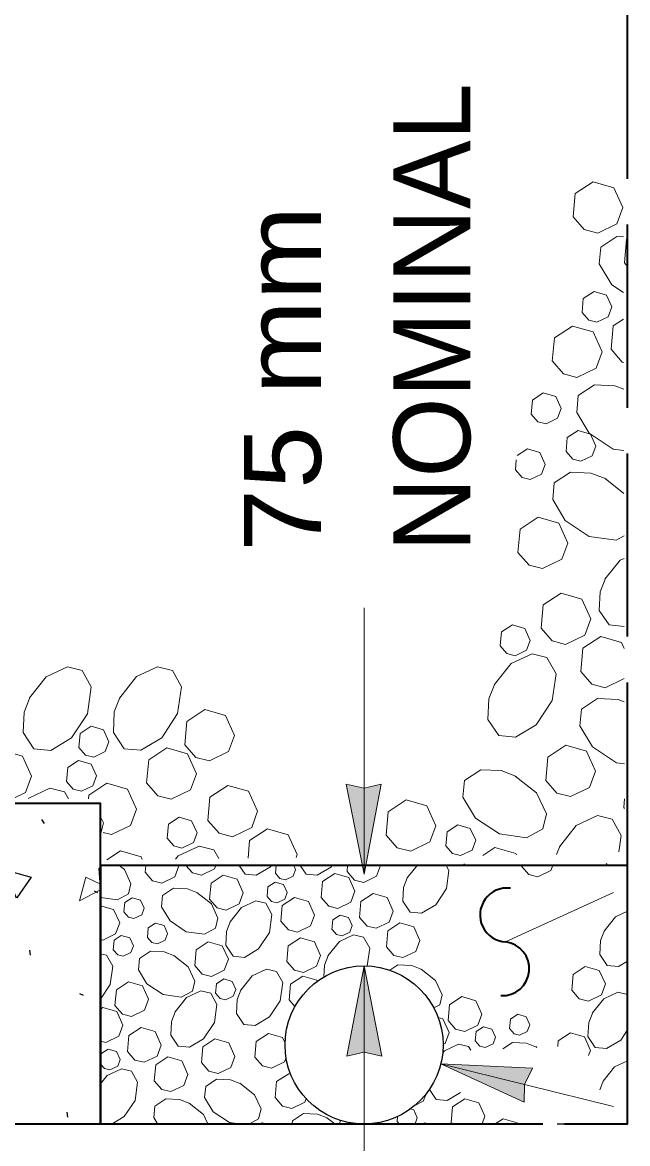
# Model space of a CAD drawing. Extents: x 17672 to 18472, y -9785 to -9267.
# Drawn here: x 17840.7 to 17868.5, y -9467.9 to -9416.4 of the extents above; entities that cross this region are included whole.
import ezdxf

# ---------------------------------------------------------------- set-up
doc = ezdxf.new("R2010")
doc.units = 0
doc.header["$LTSCALE"] = 1.4
doc.linetypes.add('LONG_DASHED', pattern=[7.5, 6, -1.5])
for name, color, linetype, lineweight in [('1', 7, 'Continuous', 13), ('15', 7, 'Continuous', 13), ('16', 7, 'Continuous', 13)]:
    doc.layers.add(name, color=color, linetype=linetype, lineweight=lineweight)
doc.layers.add('19', color=7, linetype='Continuous')

msp = doc.modelspace()

# ---------------------------------------------------------------- hatches: boundary and pattern name
at = {"layer": '16'}
for points in [[(17856.379, -9455.509), (17857.161, -9451.372), (17856.379, -9451.558), (17855.558, -9451.372)], [(17856.379, -9459.715), (17855.597, -9463.852), (17856.379, -9463.666), (17857.2, -9463.852)], [(17859.898, -9464.208), (17863.729, -9465.958), (17863.737, -9465.151), (17864.112, -9464.401)]]:
    msp.add_hatch(color=256, dxfattribs=at).paths.add_polyline_path(points)

# ---------------------------------------------------------------- linework, layer by layer
at = {"layer": '1', "linetype": 'LONG_DASHED', "lineweight": 35}
msp.add_line((17868.469, -9455.105), (17868.469, -9325.672), dxfattribs=at)
at = {"layer": '1'}
for p, q in [((17868.469, -9427.626), (17868.322, -9427.457)), ((17863.32, -9436.959), (17863.361, -9436.503)), ((17867.434, -9437.35), (17868.301, -9438.036)), ((17868.291, -9452.451), (17868.328, -9452.042)), ((17868.328, -9452.493), (17868.292, -9452.451)), ((17865.213, -9454.602), (17865.372, -9454.195)), ((17846.334, -9455.416), (17846.361, -9455.105)), ((17852.315, -9455.465), (17852.347, -9455.105)), ((17855.599, -9455.382), (17855.624, -9455.105)), ((17858.362, -9455.676), (17858.815, -9455.105)), ((17861.027, -9455.105), (17860.963, -9455.031)), ((17863.589, -9455.124), (17863.592, -9455.105)), ((17867.564, -9455.105), (17867.486, -9455.016)), ((17844.288, -9456.22), (17843.322, -9456.73)), ((17853.21, -9461.58), (17852.942, -9461.271)), ((17864.264, -9463.418), (17864.305, -9463.453)), ((17867.19, -9465.406), (17867.362, -9464.972)), ((17857.896, -9466.855), (17857.915, -9466.622)), ((17854.678, -9466.678), (17855.04, -9466.965)), ((17855.261, -9466.965), (17855.278, -9466.793)), ((17856.707, -9466.95), (17856.702, -9466.965)), ((17857.994, -9466.965), (17857.896, -9466.855)), ((17860.435, -9466.965), (17860.379, -9466.901))]:
    msp.add_line(p, q, dxfattribs=at)
at = {"layer": '1', "lineweight": 25}
for p, q in [((17841.579, -9452.997), (17841.71, -9453.175)), ((17843.991, -9456.27), (17844.149, -9456.349)), ((17844.288, -9455.897), (17844.278, -9455.908)), ((17841.073, -9459.228), (17841.048, -9458.988)), ((17843.327, -9460.977), (17843.486, -9461.055)), ((17842.791, -9466.659), (17842.766, -9466.418)), ((17865.232, -9466.965), (17865.57, -9466.965))]:
    msp.add_line(p, q, dxfattribs=at)
at = {"layer": '1'}
for points in [[(17865.97, -9425.35), (17866.065, -9424.279), (17866.891, -9423.737), (17867.841, -9424.01), (17868.253, -9424.923), (17867.979, -9425.666), (17867.1, -9426.092), (17866.481, -9425.936), (17865.97, -9425.349)], [(17868.284, -9428.821), (17867.742, -9428.463), (17867.167, -9427.507), (17867.24, -9426.74), (17867.98, -9426.244), (17868.279, -9426.258)], [(17868.321, -9427.457), (17868.417, -9426.387), (17868.469, -9426.352)], [(17866.38, -9429.739), (17866.438, -9429.097), (17866.933, -9428.771), (17867.503, -9428.935), (17867.75, -9429.482), (17867.586, -9429.929), (17867.058, -9430.184), (17866.687, -9430.091), (17866.381, -9429.738)], [(17867.715, -9431.421), (17867.811, -9430.351), (17868.286, -9430.039)], [(17865.017, -9431.97), (17865.113, -9430.9), (17865.939, -9430.358), (17866.888, -9430.631), (17867.301, -9431.544), (17867.027, -9432.288), (17866.147, -9432.713), (17865.528, -9432.558), (17865.018, -9431.97)], [(17868.29, -9432.024), (17868.226, -9432.008), (17867.715, -9431.421)], [(17868.297, -9436.072), (17867.815, -9436.003), (17866.711, -9435.274), (17866.136, -9434.318), (17866.209, -9433.551), (17866.948, -9433.055), (17867.891, -9433.099), (17868.292, -9433.256)], [(17864.049, -9434.397), (17864.106, -9433.755), (17864.602, -9433.429), (17865.172, -9433.593), (17865.419, -9434.141), (17865.255, -9434.587), (17864.727, -9434.842), (17864.356, -9434.749), (17864.05, -9434.397)], [(17865.645, -9436.118), (17865.703, -9435.476), (17866.198, -9435.151), (17866.768, -9435.315), (17867.015, -9435.862), (17866.851, -9436.308), (17866.324, -9436.564), (17865.952, -9436.471), (17865.646, -9436.118)], [(17863.406, -9436.298), (17863.873, -9435.991), (17864.443, -9436.155), (17864.69, -9436.703), (17864.526, -9437.149), (17863.998, -9437.405), (17863.627, -9437.311), (17863.321, -9436.959)], [(17868.305, -9439.981), (17867.943, -9440.181), (17866.712, -9440.007), (17865.608, -9439.277), (17865.033, -9438.322), (17865.106, -9437.554), (17865.846, -9437.059), (17866.788, -9437.102), (17867.483, -9437.375)], [(17863.441, -9440.743), (17863.536, -9439.672), (17864.363, -9439.13), (17865.312, -9439.403), (17865.725, -9440.316), (17865.45, -9441.06), (17864.571, -9441.485), (17863.952, -9441.329), (17863.441, -9440.742)], [(17867.432, -9441.977), (17868.127, -9441.1), (17868.307, -9441.016)], [(17868.313, -9444.135), (17868.307, -9444.138), (17867.617, -9444.073), (17867.17, -9443.407), (17867.21, -9442.558), (17867.455, -9441.933)], [(17862.63, -9445.035), (17862.687, -9444.393), (17863.183, -9444.068), (17863.753, -9444.232), (17864, -9444.779), (17863.836, -9445.225), (17863.308, -9445.481), (17862.937, -9445.388), (17862.63, -9445.036)], [(17866.317, -9446.208), (17866.412, -9445.138), (17867.239, -9444.596), (17868.188, -9444.869), (17868.314, -9445.149)], [(17862.355, -9446.82), (17863.127, -9445.845), (17864.093, -9445.394), (17864.77, -9445.557), (17865.186, -9446.312), (17865.013, -9447.542), (17864.283, -9448.647), (17863.327, -9449.221), (17862.56, -9449.149), (17862.064, -9448.409), (17862.108, -9447.466), (17862.381, -9446.771)], [(17841.031, -9447.422), (17841.803, -9446.448), (17842.769, -9445.996), (17843.445, -9446.159), (17843.862, -9446.914), (17843.688, -9448.145), (17842.959, -9449.249), (17842.003, -9449.824), (17841.236, -9449.752), (17840.74, -9449.011), (17840.784, -9448.069), (17841.056, -9447.373)], [(17845.169, -9447.418), (17845.941, -9446.443), (17846.907, -9445.991), (17847.584, -9446.155), (17848.001, -9446.909), (17847.827, -9448.14), (17847.097, -9449.244), (17846.141, -9449.819), (17845.374, -9449.747), (17844.878, -9449.006), (17844.922, -9448.064), (17845.195, -9447.369)], [(17868.317, -9446.529), (17867.447, -9446.951), (17866.828, -9446.795), (17866.317, -9446.208)], [(17868.324, -9450.443), (17867.96, -9450.391), (17866.856, -9449.662), (17866.281, -9448.706), (17866.353, -9447.939), (17867.093, -9447.443), (17868.036, -9447.487), (17868.319, -9447.598)], [(17838.833, -9451.435), (17838.929, -9450.365), (17839.755, -9449.823), (17840.704, -9450.096), (17841.116, -9451.008), (17840.842, -9451.752), (17840.246, -9452.041)], [(17846.405, -9451.323), (17846.5, -9450.253), (17847.327, -9449.71), (17848.276, -9449.983), (17848.688, -9450.896), (17848.414, -9451.64), (17847.535, -9452.065), (17846.916, -9451.91), (17846.406, -9451.322)], [(17863.318, -9451.003), (17864.293, -9451.775), (17864.745, -9452.741), (17864.582, -9453.418), (17863.827, -9453.834), (17862.597, -9453.661), (17861.492, -9452.932), (17860.917, -9451.975), (17860.99, -9451.209), (17861.73, -9450.713), (17862.672, -9450.756), (17863.367, -9451.029)], [(17840.98, -9452.041), (17841.001, -9452.014), (17841.966, -9451.563), (17842.643, -9451.726), (17842.817, -9452.041)], [(17843.743, -9452.041), (17843.758, -9451.878), (17844.584, -9451.335), (17845.533, -9451.608), (17845.946, -9452.521), (17845.671, -9453.265), (17844.792, -9453.691), (17844.41, -9453.595)], [(17844.288, -9452.873), (17844.42, -9453.156), (17844.288, -9453.704)], [(17865.346, -9454.244), (17866.118, -9453.269), (17867.084, -9452.817), (17867.761, -9452.981), (17868.178, -9453.735), (17868.072, -9454.482)], [(17851.057, -9454.77), (17851.129, -9453.961), (17851.956, -9453.42), (17852.905, -9453.693), (17853.317, -9454.605), (17853.266, -9454.744)], [(17847.732, -9454.81), (17847.844, -9454.669), (17848.81, -9454.217), (17849.487, -9454.381), (17849.711, -9454.786)], [(17861.83, -9454.642), (17862.386, -9454.277), (17863.336, -9454.55), (17863.369, -9454.624)], [(17844.572, -9454.848), (17845.202, -9454.434), (17846.152, -9454.707), (17846.207, -9454.828)], [(17845.146, -9455.105), (17845.383, -9455.291), (17845.687, -9455.945), (17845.577, -9456.401), (17845.067, -9456.683), (17844.288, -9456.573)], [(17847.866, -9455.105), (17847.879, -9455.129), (17847.692, -9455.632), (17847.097, -9455.918), (17846.68, -9455.813), (17846.334, -9455.416)], [(17849.572, -9455.105), (17849.516, -9455.259), (17848.923, -9455.548), (17848.504, -9455.443), (17848.209, -9455.105)], [(17852.126, -9455.105), (17852.084, -9455.168), (17851.437, -9455.556), (17850.92, -9455.507), (17850.651, -9455.105)], [(17853.158, -9455.105), (17853.241, -9455.291), (17853.131, -9455.595), (17852.773, -9455.766), (17852.523, -9455.703), (17852.315, -9455.465)], [(17854.923, -9455.105), (17854.884, -9455.163), (17854.236, -9455.553), (17853.717, -9455.504), (17853.45, -9455.105)], [(17857.138, -9455.105), (17856.957, -9455.597), (17856.364, -9455.884), (17855.945, -9455.779), (17855.599, -9455.382)], [(17860.151, -9455.105), (17860.276, -9455.33), (17860.158, -9456.163), (17859.665, -9456.908), (17859.018, -9457.298), (17858.501, -9457.249), (17858.165, -9456.749), (17858.195, -9456.112), (17858.379, -9455.641)], [(17860.705, -9455.105), (17860.67, -9455.119), (17860.607, -9455.105)], [(17865.036, -9455.105), (17864.947, -9455.34), (17864.354, -9455.627), (17863.935, -9455.521), (17863.589, -9455.124)], [(17843.322, -9456.73), (17843.619, -9455.636), (17844.288, -9455.967)], [(17854.413, -9456.57), (17854.479, -9455.847), (17855.038, -9455.48), (17855.68, -9455.663), (17855.957, -9456.281), (17855.773, -9456.783), (17855.178, -9457.073), (17854.761, -9456.967), (17854.415, -9456.57)], [(17848.714, -9456.347), (17849.374, -9456.869), (17849.678, -9457.521), (17849.567, -9457.98), (17849.058, -9458.261), (17848.224, -9458.144), (17847.479, -9457.651), (17847.089, -9457.004), (17847.138, -9456.484), (17847.638, -9456.149), (17848.276, -9456.181), (17848.746, -9456.364)], [(17851.93, -9456.524), (17851.969, -9456.09), (17852.305, -9455.869), (17852.69, -9455.98), (17852.857, -9456.35), (17852.746, -9456.651), (17852.391, -9456.825), (17852.138, -9456.761), (17851.933, -9456.524)], [(17850.239, -9457.695), (17850.761, -9457.036), (17851.413, -9456.732), (17851.871, -9456.842), (17852.153, -9457.352), (17852.035, -9458.183), (17851.543, -9458.931), (17850.896, -9459.32), (17850.379, -9459.271), (17850.043, -9458.769), (17850.072, -9458.132), (17850.256, -9457.663)], [(17844.288, -9456.953), (17844.891, -9457.124), (17845.17, -9457.742), (17844.984, -9458.244), (17844.391, -9458.533), (17844.288, -9458.507)], [(17854.908, -9458.038), (17854.947, -9457.605), (17855.283, -9457.384), (17855.67, -9457.497), (17855.835, -9457.864), (17855.724, -9458.168), (17855.369, -9458.34), (17855.116, -9458.276), (17854.91, -9458.038)], [(17867.393, -9458.117), (17867.916, -9457.458), (17868.469, -9457.2)], [(17854.724, -9459.244), (17855.246, -9458.587), (17855.898, -9458.281), (17856.357, -9458.391), (17856.638, -9458.901), (17856.523, -9459.717)], [(17868.469, -9459.489), (17868.05, -9459.739), (17867.531, -9459.69), (17867.197, -9459.19), (17867.227, -9458.553), (17867.411, -9458.083)], [(17844.288, -9459.156), (17844.565, -9459.222), (17844.847, -9459.732), (17844.729, -9460.565), (17844.288, -9461.232)], [(17847.653, -9459.237), (17848.312, -9459.757), (17848.616, -9460.411), (17848.506, -9460.867), (17847.996, -9461.149), (17847.163, -9461.031), (17846.418, -9460.538), (17846.028, -9459.894), (17846.077, -9459.374), (17846.577, -9459.038), (17847.214, -9459.068), (17847.685, -9459.252)], [(17854.531, -9460.22), (17854.558, -9459.683), (17854.741, -9459.212)], [(17850.732, -9460.82), (17851.254, -9460.163), (17851.906, -9459.857), (17852.364, -9459.967), (17852.646, -9460.477), (17852.528, -9461.31), (17852.035, -9462.056), (17851.388, -9462.443), (17850.871, -9462.394), (17850.535, -9461.896), (17850.565, -9461.257), (17850.749, -9460.788)], [(17857.56, -9459.911), (17857.928, -9459.666), (17858.565, -9459.695), (17859.033, -9459.879)], [(17859.001, -9459.862), (17859.661, -9460.384), (17859.964, -9461.038), (17859.854, -9461.494), (17859.585, -9461.644)], [(17852.942, -9461.271), (17853.006, -9460.548), (17853.565, -9460.183), (17854.207, -9460.367), (17854.232, -9460.418)], [(17847.714, -9461.823), (17848.236, -9461.163), (17848.888, -9460.857), (17849.347, -9460.967), (17849.629, -9461.477), (17849.511, -9462.31), (17849.018, -9463.056), (17848.371, -9463.445), (17847.854, -9463.396), (17847.518, -9462.896), (17847.548, -9462.259), (17847.732, -9461.788)], [(17866.852, -9461.879), (17867.374, -9461.22), (17868.026, -9460.916), (17868.469, -9461.021)], [(17844.288, -9461.693), (17844.391, -9461.627), (17845.033, -9461.81), (17845.31, -9462.428), (17845.126, -9462.931), (17844.531, -9463.22), (17844.288, -9463.159)], [(17868.469, -9462.639), (17868.156, -9463.114), (17867.509, -9463.502), (17866.989, -9463.455), (17866.653, -9462.955), (17866.685, -9462.315), (17866.869, -9461.847)], [(17859.778, -9462.083), (17860.001, -9462.146), (17860.281, -9462.764), (17860.094, -9463.266), (17860.004, -9463.31)], [(17861.482, -9463.156), (17861.521, -9462.72), (17861.857, -9462.502), (17862.241, -9462.612), (17862.408, -9462.982), (17862.298, -9463.284), (17861.94, -9463.458), (17861.69, -9463.394), (17861.484, -9463.156)], [(17851.369, -9463.901), (17851.433, -9463.178), (17851.991, -9462.813), (17852.634, -9462.997), (17852.754, -9463.264)], [(17865.264, -9463.413), (17865.288, -9463.154), (17865.847, -9462.788), (17866.487, -9462.972), (17866.766, -9463.59), (17866.68, -9463.82)], [(17844.288, -9463.889), (17844.3, -9463.752), (17844.636, -9463.531), (17845.021, -9463.641), (17845.187, -9464.014), (17845.077, -9464.313), (17844.722, -9464.487), (17844.469, -9464.423), (17844.288, -9464.215)], [(17859.987, -9463.703), (17860.065, -9463.602), (17860.717, -9463.296), (17861.175, -9463.406), (17861.273, -9463.58)], [(17862.749, -9463.519), (17863.19, -9463.222), (17863.827, -9463.252), (17864.298, -9463.435)], [(17852.8, -9463.918), (17852.727, -9464.117), (17852.131, -9464.404), (17851.714, -9464.298), (17851.369, -9463.901)], [(17867.344, -9465.004), (17867.864, -9464.345), (17868.469, -9464.063)], [(17844.288, -9465.124), (17844.599, -9464.735), (17845.251, -9464.428), (17845.709, -9464.538), (17845.991, -9465.048), (17845.874, -9465.882), (17845.381, -9466.627), (17844.817, -9466.965)], [(17850.685, -9466.965), (17850.2, -9466.896), (17849.452, -9466.404), (17849.065, -9465.757), (17849.114, -9465.239), (17849.614, -9464.904), (17850.251, -9464.933), (17850.722, -9465.117)], [(17850.687, -9465.1), (17851.347, -9465.622), (17851.653, -9466.274), (17851.543, -9466.732), (17851.121, -9466.965)], [(17852.298, -9465.747), (17852.364, -9465.024), (17852.923, -9464.659), (17853.011, -9464.683)], [(17859.202, -9465.614), (17859.207, -9465.622), (17859.094, -9465.923), (17858.739, -9466.097), (17858.734, -9466.095)], [(17860.81, -9465.519), (17860.2, -9465.884), (17859.683, -9465.835), (17859.376, -9465.379)], [(17846.91, -9466.965), (17846.732, -9466.666), (17846.781, -9466.149), (17847.281, -9465.813), (17847.918, -9465.842), (17848.386, -9466.029)], [(17848.354, -9466.011), (17849.013, -9466.531), (17849.214, -9466.965)], [(17853.717, -9465.801), (17853.656, -9465.962), (17853.062, -9466.249), (17852.643, -9466.144), (17852.3, -9465.747)], [(17860.379, -9466.901), (17860.442, -9466.176), (17861.001, -9465.811), (17861.643, -9465.994), (17861.923, -9466.612), (17861.793, -9466.965)], [(17853.089, -9466.965), (17853.104, -9466.815), (17853.604, -9466.48), (17854.241, -9466.511), (17854.712, -9466.695)], [(17858.513, -9466.271), (17858.656, -9466.311), (17858.822, -9466.681), (17858.717, -9466.965)], [(17851.626, -9466.965), (17851.702, -9466.916), (17851.874, -9466.965)], [(17859.062, -9466.965), (17859.148, -9466.909), (17859.344, -9466.965)], [(17862.398, -9466.965), (17862.759, -9466.73), (17863.401, -9466.913), (17863.425, -9466.965)]]:
    msp.add_lwpolyline(points, dxfattribs=at)
for points in [[(17864.498, -9444.22), (17864.593, -9443.15), (17865.419, -9442.608), (17866.368, -9442.881), (17866.781, -9443.793), (17866.507, -9444.537), (17865.628, -9444.963), (17865.009, -9444.807)], [(17848.158, -9449.566), (17848.253, -9448.496), (17849.08, -9447.954), (17850.029, -9448.227), (17850.442, -9449.139), (17850.167, -9449.883), (17849.288, -9450.309), (17848.669, -9450.153)], [(17843.3, -9449.688), (17843.357, -9449.046), (17843.853, -9448.721), (17844.422, -9448.885), (17844.67, -9449.432), (17844.505, -9449.879), (17843.978, -9450.134), (17843.607, -9450.041)], [(17864.717, -9451.206), (17864.812, -9450.136), (17865.639, -9449.593), (17866.588, -9449.866), (17867.001, -9450.779), (17866.726, -9451.523), (17865.847, -9451.949), (17865.228, -9451.793)], [(17842.732, -9451.254), (17842.789, -9450.612), (17843.285, -9450.287), (17843.855, -9450.451), (17844.102, -9450.998), (17843.938, -9451.445), (17843.41, -9451.7), (17843.039, -9451.607)], [(17849.215, -9453.043), (17849.31, -9451.973), (17850.136, -9451.431), (17851.085, -9451.704), (17851.498, -9452.617), (17851.224, -9453.36), (17850.345, -9453.787), (17849.726, -9453.631)], [(17857.391, -9453.709), (17857.486, -9452.639), (17858.312, -9452.097), (17859.262, -9452.37), (17859.674, -9453.282), (17859.4, -9454.026), (17858.521, -9454.452), (17857.902, -9454.296)], [(17847.347, -9453.859), (17847.404, -9453.217), (17847.9, -9452.891), (17848.47, -9453.055), (17848.717, -9453.603), (17848.553, -9454.049), (17848.025, -9454.305), (17847.654, -9454.211)], [(17860.13, -9454.207), (17860.187, -9453.565), (17860.683, -9453.24), (17861.252, -9453.404), (17861.5, -9453.951), (17861.336, -9454.398), (17860.808, -9454.653), (17860.437, -9454.56)], [(17849.295, -9456.646), (17849.359, -9455.921), (17849.92, -9455.556), (17850.56, -9455.739), (17850.839, -9456.357), (17850.653, -9456.859), (17850.06, -9457.149), (17849.641, -9457.043)], [(17845.364, -9457.239), (17845.403, -9456.806), (17845.739, -9456.585), (17846.121, -9456.698), (17846.29, -9457.065), (17846.178, -9457.367), (17845.822, -9457.541), (17845.57, -9457.477)], [(17852.56, -9457.668), (17852.626, -9456.945), (17853.183, -9456.578), (17853.825, -9456.764), (17854.104, -9457.379), (17853.918, -9457.882), (17853.325, -9458.171), (17852.906, -9458.065)], [(17856.173, -9457.487), (17856.236, -9456.764), (17856.795, -9456.399), (17857.437, -9456.582), (17857.717, -9457.2), (17857.531, -9457.703), (17856.937, -9457.989), (17856.518, -9457.884)], [(17846.442, -9458.404), (17846.482, -9457.97), (17846.817, -9457.749), (17847.202, -9457.859), (17847.369, -9458.23), (17847.258, -9458.531), (17846.901, -9458.705), (17846.651, -9458.641)], [(17857.403, -9458.833), (17857.467, -9458.107), (17858.026, -9457.742), (17858.668, -9457.926), (17858.945, -9458.543), (17858.761, -9459.046), (17858.165, -9459.335), (17857.746, -9459.23)], [(17844.871, -9458.972), (17844.91, -9458.538), (17845.244, -9458.318), (17845.629, -9458.428), (17845.798, -9458.798), (17845.685, -9459.1), (17845.33, -9459.274), (17845.077, -9459.21)], [(17852.837, -9459.516), (17852.901, -9458.793), (17853.46, -9458.428), (17854.102, -9458.612), (17854.381, -9459.23), (17854.195, -9459.732), (17853.602, -9460.019), (17853.183, -9459.913)], [(17848.611, -9459.693), (17848.675, -9458.97), (17849.234, -9458.605), (17849.876, -9458.788), (17850.156, -9459.406), (17849.969, -9459.909), (17849.376, -9460.195), (17848.957, -9460.09)], [(17865.908, -9460.83), (17865.972, -9460.105), (17866.531, -9459.739), (17867.173, -9459.923), (17867.45, -9460.541), (17867.266, -9461.043), (17866.67, -9461.33), (17866.254, -9461.227)], [(17844.952, -9461.529), (17845.018, -9460.806), (17845.575, -9460.44), (17846.217, -9460.624), (17846.496, -9461.242), (17846.31, -9461.744), (17845.717, -9462.031), (17845.298, -9461.926)], [(17849.565, -9460.965), (17849.604, -9460.531), (17849.94, -9460.313), (17850.325, -9460.423), (17850.491, -9460.793), (17850.381, -9461.095), (17850.023, -9461.266), (17849.773, -9461.203)], [(17860.237, -9462.215), (17860.303, -9461.492), (17860.862, -9461.124), (17861.504, -9461.31), (17861.781, -9461.926), (17861.594, -9462.428), (17861.001, -9462.717), (17860.582, -9462.612)], [(17863.055, -9462.587), (17863.092, -9462.154), (17863.428, -9461.933), (17863.813, -9462.043), (17863.979, -9462.413), (17863.869, -9462.715), (17863.514, -9462.889), (17863.261, -9462.825)], [(17845.526, -9463.634), (17845.589, -9462.911), (17846.148, -9462.546), (17846.79, -9462.73), (17847.07, -9463.347), (17846.883, -9463.85), (17846.29, -9464.136), (17845.871, -9464.031)], [(17848.915, -9464.151), (17848.979, -9463.428), (17849.538, -9463.063), (17850.18, -9463.247), (17850.457, -9463.864), (17850.273, -9464.367), (17849.68, -9464.654), (17849.261, -9464.548)], [(17846.756, -9464.98), (17846.82, -9464.254), (17847.379, -9463.889), (17848.021, -9464.073), (17848.298, -9464.69), (17848.114, -9465.193), (17847.518, -9465.482), (17847.099, -9465.377)]]:
    msp.add_lwpolyline(points, close=True, dxfattribs=at)
at = {"layer": '1', "lineweight": 35}
msp.add_lwpolyline([(17791.158, -9452.266), (17752.427, -9452.266), (17752.427, -9466.965), (17844.288, -9466.965), (17844.288, -9452.266), (17815.601, -9452.266)], close=True, dxfattribs=at)
at = {"layer": '1', "lineweight": 25}
for points in [[(17840.43, -9456.612), (17839.899, -9455.303), (17841.111, -9455.649), (17840.446, -9456.593)], [(17844.278, -9455.908), (17844.226, -9455.231), (17844.288, -9455.238)]]:
    msp.add_lwpolyline(points, dxfattribs=at)
at = {"layer": '1', "lineweight": 35}
msp.add_lwpolyline([(17865.57, -9466.965), (17868.469, -9466.965), (17868.469, -9455.105), (17844.288, -9455.105), (17844.288, -9466.965), (17864.585, -9466.965)], dxfattribs=at)
at = {"layer": '1', "lineweight": 25}
msp.add_circle((17856.379, -9463.34), 3.626, dxfattribs=at)
at = {"layer": '15'}
for p, q in [((17856.379, -9455.509), (17856.379, -9443.293)), ((17867.827, -9456.352), (17862.876, -9458.614)), ((17856.379, -9459.715), (17856.379, -9469.411)), ((17867.825, -9466.156), (17859.898, -9464.208))]:
    msp.add_line(p, q, dxfattribs=at)
at = {"layer": '16'}
for points in [[(17856.379, -9455.509), (17857.161, -9451.372), (17856.379, -9451.558), (17855.558, -9451.372)], [(17856.379, -9459.715), (17855.597, -9463.852), (17856.379, -9463.666), (17857.2, -9463.852)], [(17859.898, -9464.208), (17863.729, -9465.958), (17863.737, -9465.151), (17864.112, -9464.401)]]:
    msp.add_lwpolyline(points, close=True, dxfattribs=at)
at = {"layer": '16', "lineweight": 35}
for centre, start, end in [((17862.937, -9457.378), 82.8424, 267.1576), ((17862.721, -9459.842), 267.1576, 82.8424)]:
    msp.add_arc(centre, 1.238, start, end, dxfattribs=at)

# ---------------------------------------------------------------- texts
at = {"layer": '19'}
msp.add_text('NOMINAL', height=3.529, rotation=90, dxfattribs=at).set_placement((17861.249, -9440.715))
at = {"layer": '19', "width": 1.1}
msp.add_text('75 mm', height=3.529, rotation=90, dxfattribs=at).set_placement((17854.398, -9440.715))

doc.saveas('drawing.dxf')
